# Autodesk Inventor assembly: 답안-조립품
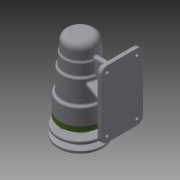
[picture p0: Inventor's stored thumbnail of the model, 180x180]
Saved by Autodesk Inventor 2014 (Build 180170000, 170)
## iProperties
Created: 2016-06
Part Number: 답안-조립품
Document SubType Name: Assembly
Designer: SEC
Author: SEC
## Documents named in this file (12)
- C:\Documents and Settings\SEC\바탕 화면\460607V1006\답안-조립품.iam
- C:\Documents and Settings\SEC\바탕 화면\460607V1006\본체.ipt
- C:\Documents and Settings\SEC\바탕 화면\460607V1006\커버.ipt
- C:\Documents and Settings\SEC\바탕 화면\460607V1006\축.ipt
- C:\Documents and Settings\SEC\바탕 화면\460607V1006\키 5 x 5 x 16.ipt
- C:\Documents and Settings\SEC\바탕 화면\460607V1006\V벨트풀리.ipt
- C:\Documents and Settings\SEC\바탕 화면\460607V1006\베어링 6004.ipt
- C:\Documents and Settings\SEC\바탕 화면\460607V1006\오일 실.ipt
- C:\Documents and Settings\SEC\바탕 화면\460607V1006\멈춤나사 M3x8.ipt
- C:\Documents and Settings\SEC\바탕 화면\460607V1006\어댑터슬리브.ipt
- C:\Documents and Settings\SEC\바탕 화면\460607V1006\베어링 51202.ipt
- C:\Documents and Settings\SEC\바탕 화면\460607V1006\볼트 M4 x 12.ipt
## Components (6 placed, 2 different names)
1. V벨트풀리:1 — 각도:1, 플러쉬:1
2. ISO 4762 M4 x 12:1 — 각도:1
3. ISO 4762 M4 x 12:2 — 각도:2
4. ISO 4762 M4 x 12:3
5. ISO 4762 M4 x 12:4
6. ISO 4762 M4 x 12:5
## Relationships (3: Angle 2, Flush 1)
- 각도:1 [Angle]: V벨트풀리:1 ↔ ISO 4762 M4 x 12:1
- 각도:2 [Angle]: ISO 4762 M4 x 12:2
- 플러쉬:1 [Flush]: V벨트풀리:1
